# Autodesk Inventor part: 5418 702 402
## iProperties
Shininess: 64.0
Length Units: 11269
Angle Units: 11279
Time Units: 11290
Mass Units: 11283
Length Display Precision: 3
Angle Display Precision: 2
Compacted: True
Part Number: 5418 702 402
Document SubType Name: Modeling
Created: 2004-09
Material: Stahl (schweißbar)
Designer: F. Selent
Manufacturer: Standard
Standards Organization: Custom
Mass: 28310.3 g
Surface Area: 3322.95 cm^2
Volume: 3601.82 cm^3
Density: 7.86 g/cm^3
Density: 0.0
Volumn: 0.0
Area: 0.0
PropertySet Name: Model Information
Control State: 0
Master: False
Checked Out: False
Author: F. Selent
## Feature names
1. Drehung1 [Revolution]
2. Rundung1 [Fillet]
3. Extrusion1
4. Extrusion2
5. Extrusion3
6. Extrusion4
7. Extrusion5
8. Extrusion6
9. Fase1 [Chamfer]
10. Fase2 [Chamfer]
11. Extrusion7
12. Extrusion8
13. Bohrung1 [Hole]
14. Bohrung2 [Hole]
15. Umdrehung2 [Revolution]
16. Umdrehung3 [Revolution]
17. Spiegeln1 [Mirror]
